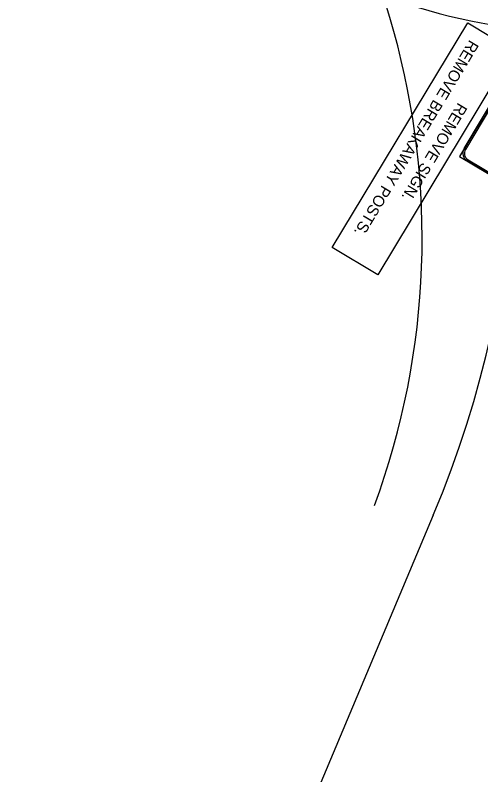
# Model space of a CAD drawing. Extents: x 2338610 to 2351914, y 366540 to 376484.
# Drawn here: x 2345982 to 2346464, y 368623 to 369410 of the extents above; entities that cross this region are included whole.
import ezdxf

# ---------------------------------------------------------------- set-up
doc = ezdxf.new("R2010")
doc.units = 0
for name, color, linetype in [('RD_HC_Cl', 7, 'Continuous'), ('RD_PD_SW', 7, 'Continuous'), ('TR SN EXISTING - BREAK-AWAY SIGN SUPPORTS', 7, 'Continuous'), ('TR SN EXTRUDED PANEL SIGNS - GROUND MOUNTED', 7, 'Continuous')]:
    doc.layers.add(name, color=color, linetype=linetype)

msp = doc.modelspace()

# ---------------------------------------------------------------- linework, layer by layer
at = {"layer": 'RD_HC_Cl'}
msp.add_line((2346414.93, 368892.18), (2346073.65, 368081.29), dxfattribs=at)
msp.add_line((2346414.93, 368892.18), (2346073.65, 368081.29), dxfattribs=at)
msp.add_line((2346414.93, 368892.18), (2346073.65, 368081.29), dxfattribs=at)
msp.add_line((2346414.93, 368892.18), (2346073.65, 368081.29), dxfattribs=at)
for centre, radius, start, end in [((2345401.07, 369318.89), 1100, 337.175, 58.13524), ((2345401.07, 369318.89), 1100, 337.175, 58.13524), ((2345401.07, 369318.89), 1100, 337.175, 58.13524), ((2345401.07, 369318.89), 1100, 337.175, 58.13524), ((2345603.44, 369178.93), 800, 339.77456, 51.32478), ((2345603.44, 369178.93), 800, 339.77456, 51.32478), ((2345603.44, 369178.93), 800, 339.77456, 51.32478), ((2345603.44, 369178.93), 800, 339.77456, 51.32478)]:
    msp.add_arc(centre, radius, start, end, dxfattribs=at)
at = {"layer": 'RD_PD_SW'}
msp.add_arc((2346569.92, 369970.88), 578, 225.25217, 260.63391, dxfattribs=at)
at = {"layer": 'TR SN EXISTING - BREAK-AWAY SIGN SUPPORTS'}
msp.add_lwpolyline([(2346497.79, 369374.28), (2346357.39, 369141.36), (2346310.36, 369169.71), (2346450.76, 369402.63)], close=True, dxfattribs=at)
at = {"layer": 'TR SN EXTRUDED PANEL SIGNS - GROUND MOUNTED'}
for p, q in [((2346448.31, 369271.35), (2346446.97, 369272.15)), ((2346450.22, 369259.29), (2346451.02, 369260.63))]:
    msp.add_line(p, q, dxfattribs=at)
for points in [[(2346504.61, 369368.76), (2346442.17, 369264.1), (2346498.52, 369230.47), (2346560.97, 369335.13), (2346504.61, 369368.76), (2346504.61, 369368.76)], [(2346501.15, 369359.91), (2346448.31, 369271.35), (2346446.97, 369272.15), (2346499.81, 369360.71), (2346501.15, 369359.91), (2346501.15, 369359.91)], [(2346451.02, 369260.63), (2346491.27, 369236.62), (2346490.47, 369235.28), (2346450.22, 369259.29), (2346451.02, 369260.63), (2346451.02, 369260.63)]]:
    msp.add_lwpolyline(points, close=True, dxfattribs=at)
for radius in [9.38, 7.81]:
    msp.add_arc((2346455.02, 369267.34), radius, 149.17857, 239.17878, dxfattribs=at)

# ---------------------------------------------------------------- texts
at = {"layer": 'TR SN EXISTING - BREAK-AWAY SIGN SUPPORTS'}
for s, p in [('REMOVE BREAKAWAY POSTS.', (2346452.75, 369385.66)), ('REMOVE SIGN.', (2346440.88, 369320.56))]:
    msp.add_text(s, height=11.7187, rotation=238.91986, dxfattribs=at).set_placement(p)

doc.saveas('drawing.dxf')
